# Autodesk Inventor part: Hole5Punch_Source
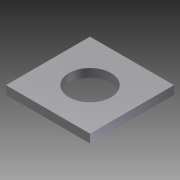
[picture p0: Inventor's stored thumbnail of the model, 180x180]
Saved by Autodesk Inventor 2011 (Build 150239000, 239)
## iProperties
Created: 2007-02
Part Number: Hole5Punch_Source
Material: Default
Document SubType Name: Sheet Metal
Designer: Autodesk, Inc.
Mass: 0.080365 g
Surface Area: 2.16438 cm^2
Volume: 0.080365 cm^3
Density: 1 g/cm^3
Sheet Metal Rule: 1 mm
Author: Autodesk, Inc.
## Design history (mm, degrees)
node "Face1"
  sketch "Sketch1"
    geometry: L1 (-5, 5)-(5, 5); L2 (5, 5)-(5, -5); L3 (5, -5)-(-5, -5); L4 (-5, -5)-(-5, 5); L5 (-5, 5)-(5, -5); 2 further points
    constraints: 10 end point, 2 parallel, 1 coincident, 1 horizontal, 1 midpoint, 1 perpendicular
    dimensions: "d0" = 10 distance of L2.end L3.end; "d1" = 10 distance of L1.end L2.end (= d0)
sketch "Sketch2"
  geometry: C1 r 2.5 at (0, 0); 2 further points
  constraints: 2 coincident, 1 centre point
  dimensions: "d3" = 5 diameter of C1
cut "Cut1" sketch "Sketch2" dims "d4" = 1 (= Thickness), "d5" = 0
body "Solid1"
face "Plate1" dims "Thickness" = 1
other parameters: "BendRadius" = 0.5, "BendReliefWidth" = 1 (= Thickness), "BendReliefDepth" = 0.5 (= 0.5 x Thickness), "CornerReliefSize" = 4 (= 4 x Thickness), "SeamGap" = 0.01, "MinimumRemnant" = 2 (= 2 x Thickness), "TransitionRadius" = 0.5 (= BendRadius), "JacobiRadiusSize" = 1 (= Thickness), "d2" = 0.5 (= BendRadius), "GapSize" = 1 (= Thickness)
